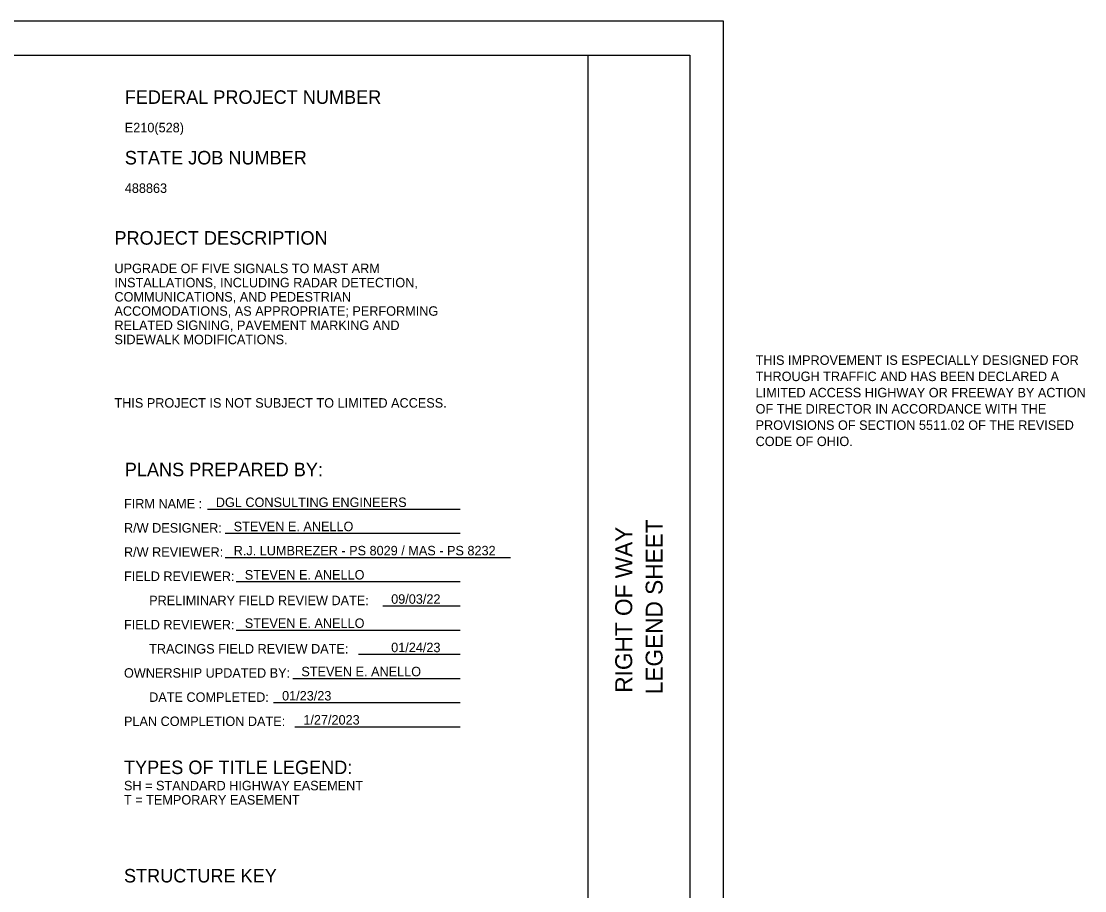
# Model space of a CAD drawing. Extents: x 0 to 39.3, y -3.9 to 22.
# Drawn here: x 23.62 to 39.34, y 9.16 to 22 of the extents above; entities that cross this region are included whole.
import ezdxf

# ---------------------------------------------------------------- set-up
doc = ezdxf.new("R2010")
doc.units = 0
for name, color, linetype in [('SH_Border', 7, 'Continuous'), ('SH_Cut_Line', 7, 'Continuous'), ('SH_Data', 7, 'Continuous'), ('SH_Text', 7, 'Continuous')]:
    doc.layers.add(name, color=color, linetype=linetype)

msp = doc.modelspace()

# ---------------------------------------------------------------- linework, layer by layer
at = {"layer": 'SH_Border'}
msp.add_line((32, 0.5), (32, 21.5), dxfattribs=at)
msp.add_lwpolyline([(1.5, 21.5), (33.5, 21.5), (33.5, 0.5), (1.5, 0.5)], close=True, dxfattribs=at)
at = {"layer": 'SH_Cut_Line'}
msp.add_lwpolyline([(0, 0), (34, 0), (34, 22), (0, 22)], close=True, dxfattribs=at)
at = {"layer": 'SH_Text'}
for p, q in [((26.373, 14.794), (30.11, 14.794)), ((26.637, 14.437), (30.11, 14.437)), ((26.637, 14.08), (30.85, 14.08)), ((26.801, 13.723), (30.11, 13.723)), ((28.965, 13.365), (30.11, 13.365)), ((26.801, 13.008), (30.11, 13.008)), ((28.607, 12.651), (30.11, 12.651)), ((27.637, 12.294), (30.11, 12.294)), ((27.352, 11.937), (30.11, 11.937)), ((27.667, 11.58), (30.11, 11.58))]:
    msp.add_line(p, q, dxfattribs=at)

# ---------------------------------------------------------------- texts
at = {"layer": 'SH_Data'}
for s, p in [('LEGEND SHEET', (33.1, 12.06)), ('RIGHT OF WAY', (32.65, 12.082))]:
    msp.add_text(s, height=0.25, rotation=90, dxfattribs=at).set_placement(p)
at = {"layer": 'SH_Text'}
for s, height, p in [('FEDERAL PROJECT NUMBER', 0.2, (25.153, 20.78)), ('E210(528)', 0.14, (25.153, 20.36)), ('STATE JOB NUMBER', 0.2, (25.153, 19.885)), ('488863', 0.14, (25.153, 19.465)), ('PROJECT DESCRIPTION', 0.2, (25, 18.7)), ('UPGRADE OF FIVE SIGNALS TO MAST ARM', 0.14, (25, 18.28)), ('INSTALLATIONS, INCLUDING RADAR DETECTION,', 0.14, (25, 18.07)), ('COMMUNICATIONS, AND PEDESTRIAN', 0.14, (25, 17.86)), ('ACCOMODATIONS, AS APPROPRIATE; PERFORMING', 0.14, (25, 17.65)), ('RELATED SIGNING, PAVEMENT MARKING AND', 0.14, (25, 17.44)), ('SIDEWALK MODIFICATIONS.', 0.14, (25, 17.23)), ('THIS IMPROVEMENT IS ESPECIALLY DESIGNED FOR', 0.14, (34.474, 16.925)), ('THROUGH TRAFFIC AND HAS BEEN DECLARED A', 0.14, (34.474, 16.685)), ('LIMITED ACCESS HIGHWAY OR FREEWAY BY ACTION', 0.14, (34.474, 16.445)), ('THIS PROJECT IS NOT SUBJECT TO LIMITED ACCESS.', 0.14, (25, 16.293)), ('OF THE DIRECTOR IN ACCORDANCE WITH THE', 0.14, (34.474, 16.205)), ('PROVISIONS OF SECTION 5511.02 OF THE REVISED', 0.14, (34.474, 15.965)), ('CODE OF OHIO.', 0.14, (34.474, 15.725)), ('PLANS PREPARED BY:', 0.2, (25.153, 15.279)), ('FIRM NAME :', 0.14, (25.141, 14.804)), ('DGL CONSULTING ENGINEERS', 0.14, (26.498, 14.825)), ('R/W DESIGNER:', 0.14, (25.141, 14.447)), ('STEVEN E. ANELLO', 0.14, (26.762, 14.468)), ('R/W REVIEWER:', 0.14, (25.141, 14.09)), ('R.J. LUMBREZER - PS 8029 / MAS - PS 8232', 0.14, (26.762, 14.111)), ('FIELD REVIEWER:', 0.14, (25.141, 13.733)), ('STEVEN E. ANELLO', 0.14, (26.926, 13.754)), ('PRELIMINARY FIELD REVIEW DATE:', 0.14, (25.513, 13.375)), ('09/03/22', 0.14, (29.089, 13.396)), ('FIELD REVIEWER:', 0.14, (25.141, 13.018)), ('STEVEN E. ANELLO', 0.14, (26.926, 13.039)), ('TRACINGS FIELD REVIEW DATE:', 0.14, (25.513, 12.661)), ('01/24/23', 0.14, (29.089, 12.681)), ('OWNERSHIP UPDATED BY:', 0.14, (25.141, 12.304)), ('STEVEN E. ANELLO', 0.14, (27.762, 12.325)), ('01/23/23', 0.14, (27.477, 11.967)), ('DATE COMPLETED:', 0.14, (25.513, 11.947)), ('PLAN COMPLETION DATE:', 0.14, (25.141, 11.59)), ('1/27/2023', 0.14, (27.791, 11.611)), ('TYPES OF TITLE LEGEND:', 0.2, (25.141, 10.88)), ('SH = STANDARD HIGHWAY EASEMENT', 0.14, (25.141, 10.64)), ('T = TEMPORARY EASEMENT', 0.14, (25.141, 10.43)), ('STRUCTURE KEY', 0.2, (25.141, 9.279))]:
    msp.add_text(s, height=height, dxfattribs=at).set_placement(p)

doc.saveas('drawing.dxf')
